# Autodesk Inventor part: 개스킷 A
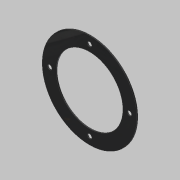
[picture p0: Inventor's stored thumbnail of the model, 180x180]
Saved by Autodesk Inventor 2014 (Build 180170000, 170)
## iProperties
Created: 2019-10
Part Number: 개스킷 A
Material: 고무
Document SubType Name: Modeling
Designer: mduedu
Density: 1 g/cm^3
Appearance: 고무 - 검은색 - 버전 1.1
Author: mduedu
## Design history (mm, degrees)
sketch "스케치1"
  geometry: C1 r 47.5 at (0, 0); C2 r 33.5 at (0, 0); 1 further point
  constraints: 2 centre point, 2 coincident
  dimensions: "d0" = 95 diameter of C1; "d1" = 67 diameter of C2
extrude "돌출1" new body sketch "스케치1" distance "d2" = 1; taper "d3" = 0 deg
sketch "스케치2" dims "d4" = 80
  geometry: C1 r 2.25 at (0, 40); 2 further points
  constraints: 2 vertical alignment, 1 centre point, 1 coincident, 2 other
  dimensions: "d5" = 4.5 diameter of C1
extrude "돌출2" cut sketch "스케치2" stored distance "d6" = 1; taper "d7" = 0 deg
node "솔리드1"
pattern_circular "원형 패턴1" dims angle "d9" = 360 deg
